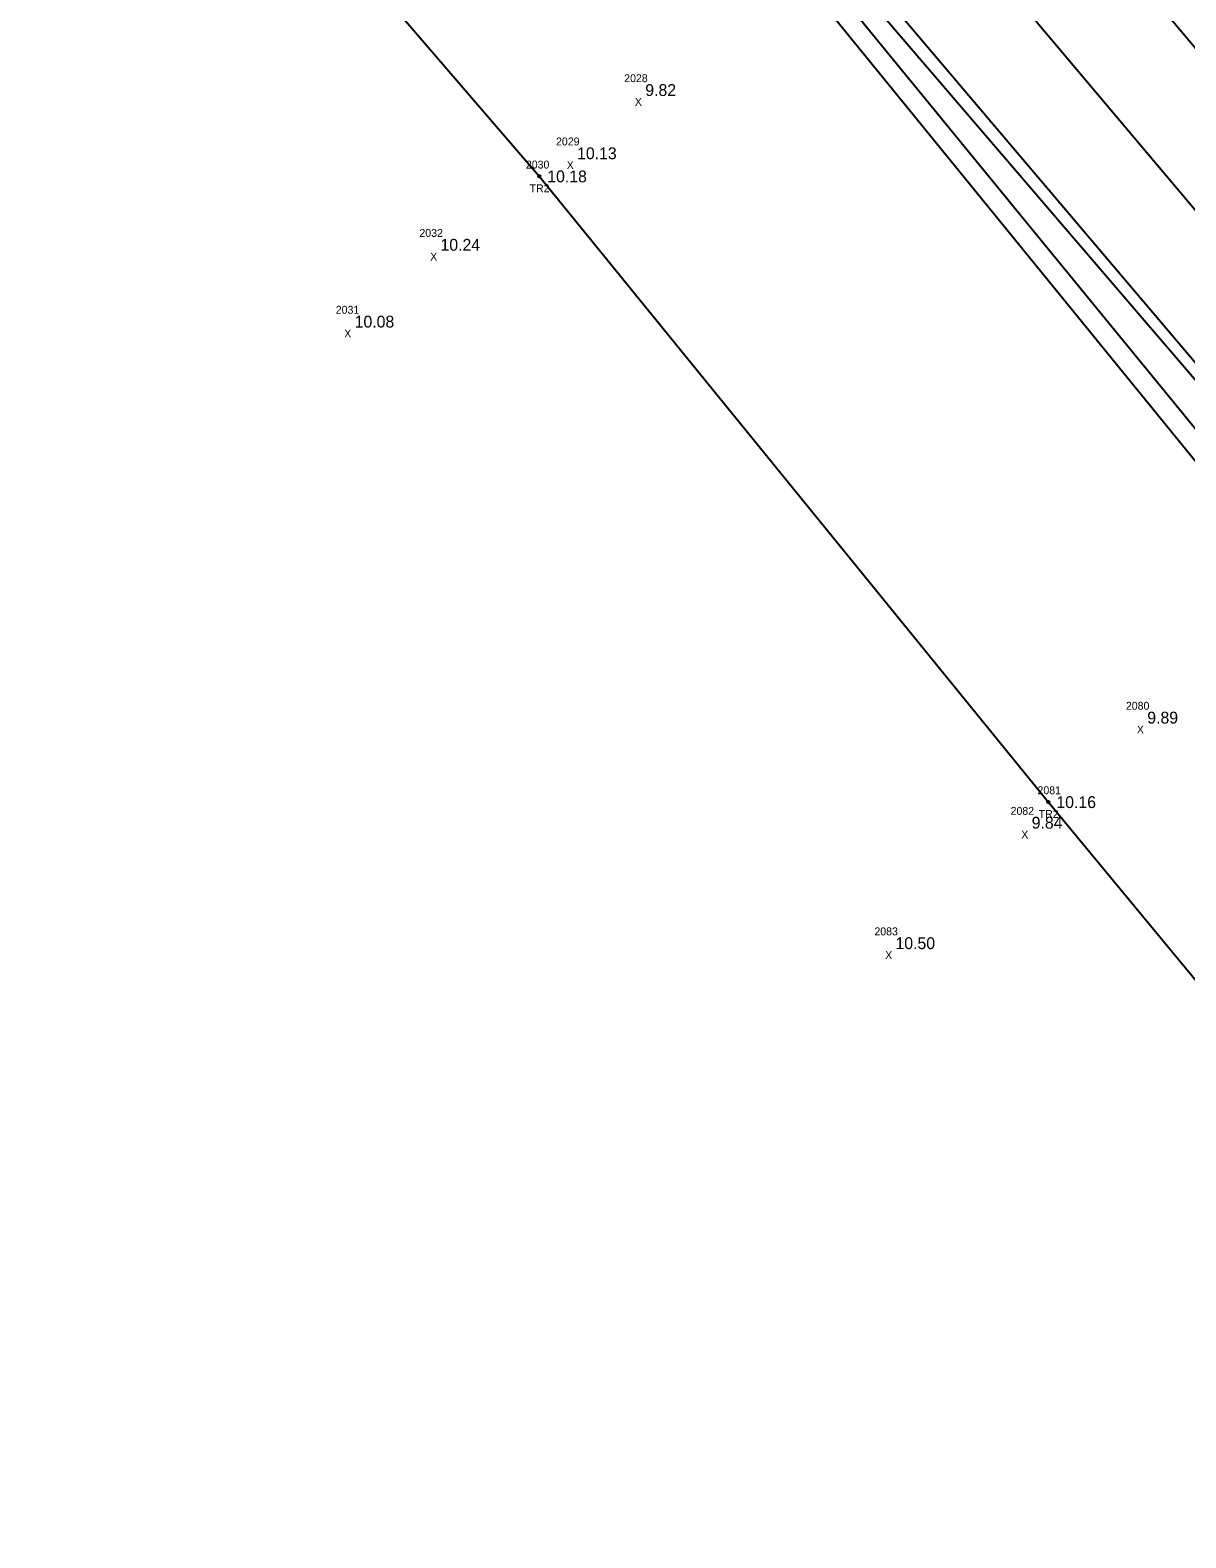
# Model space of a CAD drawing. Extents: x 2042117 to 2045853, y 303080 to 309569.
# Drawn here: x 2044074.2 to 2044220.7, y 304811.9 to 305002.9 of the extents above; entities that cross this region are included whole.
import ezdxf

# ---------------------------------------------------------------- set-up
doc = ezdxf.new("R2010")
doc.units = 0
for name, color, linetype in [('RD_EX_H2O', 7, 'Continuous'), ('RD_EX_Misc_txCode', 7, 'Continuous'), ('RD_EX_Road', 7, 'Continuous'), ('RD_EX_TX_Misc_ELEV', 7, 'Continuous'), ('RD_EX_TX_VEG_ELEV', 7, 'Continuous'), ('RD_EX_VEG', 7, 'Continuous'), ('RD_EX_VEG_txCode', 7, 'Continuous'), ('RD_HC_Cl', 7, 'Continuous'), ('RD_SMD_Locator', 7, 'Continuous')]:
    doc.layers.add(name, color=color, linetype=linetype)

msp = doc.modelspace()

# ---------------------------------------------------------------- linework, layer by layer
at = {"layer": 'RD_EX_H2O'}
for points in [[(2044112.24, 305091.58), (2044175.46, 305015.53), (2044240.61, 304938.74), (2044304.53, 304862.04), (2044368.54, 304785.1), (2044433.36, 304707.39), (2044496.86, 304631.9), (2044519.88, 304601.32), (2044518.57, 304598.19)], [(2044111.06, 305090.52), (2044173.91, 305014.56), (2044239.84, 304937.67), (2044303.17, 304860.83), (2044366.77, 304784.1), (2044432.41, 304706.69), (2044494.93, 304630.14), (2044518.25, 304599.32)], [(2044110.02, 305088.49), (2044170.14, 305011.86), (2044233.99, 304933.5), (2044300.88, 304859.21), (2044363.92, 304781.65), (2044428.82, 304703.43), (2044492.29, 304628.07), (2044516.49, 304597.96), (2044518.57, 304598.19)], [(2044110.63, 305089.46), (2044172, 305013.36), (2044236.2, 304934.93), (2044301.9, 304859.82), (2044365.31, 304782.82), (2044429.99, 304704.43), (2044493.57, 304629.27), (2044517.33, 304598.48)]]:
    msp.add_lwpolyline(points, dxfattribs=at)
at = {"layer": 'RD_EX_Road'}
msp.add_lwpolyline([(2043522.11, 305820), (2043547.67, 305789.85), (2043610.72, 305713.32), (2043674.95, 305636.32), (2043738.18, 305559.62), (2043802.42, 305482.71), (2043865.72, 305405.84), (2043929.53, 305328.85), (2043994.13, 305253.28), (2044057.4, 305176.5), (2044121.27, 305100.2), (2044185.29, 305023.54), (2044249.56, 304947.28), (2044313.31, 304870.31), (2044377.09, 304793.29), (2044442, 304716.26), (2044505.92, 304639.55), (2044570.44, 304562.35), (2044634.61, 304485.93), (2044698.46, 304409.27), (2044762.46, 304332.37)], dxfattribs=at)
at = {"layer": 'RD_EX_VEG'}
msp.add_lwpolyline([(2043442.97, 305737.07), (2043459.87, 305757.29), (2043500.33, 305735.55), (2043510.29, 305716.16), (2043558.94, 305666.15), (2043625.65, 305592.92), (2043688.91, 305518.94), (2043753.11, 305437.19), (2043818.03, 305364.7), (2043877.83, 305282.82), (2043938.63, 305211.62), (2044011.48, 305138.99), (2044075.86, 305057.44), (2044138.75, 304984.38), (2044203.27, 304905.13), (2044266.06, 304829.27), (2044328.58, 304748.23), (2044394.11, 304672.51), (2044456.79, 304595.02), (2044489.64, 304560.38)], dxfattribs=at)
at = {"layer": 'RD_HC_Cl'}
msp.add_line((2043284.3, 306123.24), (2045221.31, 303804), dxfattribs=at)
at = {"layer": 'RD_SMD_Locator'}
for centre in [(2044138.75, 304984.38), (2044203.27, 304905.13)]:
    msp.add_circle(centre, 0.15, dxfattribs=at)

# ---------------------------------------------------------------- texts
at = {"layer": 'RD_EX_Misc_txCode'}
for s, p in [('2028', (2044149.5, 304996.32)), ('X', (2044150.85, 304993.32)), ('2029', (2044140.86, 304988.31)), ('X', (2044142.22, 304985.31)), ('2032', (2044123.55, 304976.72)), ('X', (2044124.91, 304973.72)), ('2031', (2044112.95, 304966.99)), ('X', (2044114.02, 304963.99)), ('2080', (2044213.08, 304916.83)), ('X', (2044214.47, 304913.83)), ('2082', (2044198.47, 304903.52)), ('X', (2044199.82, 304900.52)), ('2083', (2044181.21, 304888.26)), ('X', (2044182.57, 304885.26))]:
    msp.add_text(s, height=1, dxfattribs=at).set_placement(p)
at = {"layer": 'RD_EX_TX_Misc_ELEV'}
for s, p in [('9.82', (2044152.17, 304994.57)), ('10.13', (2044143.53, 304986.56)), ('10.24', (2044126.22, 304974.97)), ('10.08', (2044115.34, 304965.24)), ('9.89', (2044215.79, 304915.08)), ('9.84', (2044201.14, 304901.77)), ('10.50', (2044183.88, 304886.51))]:
    msp.add_text(s, height=1.5, dxfattribs=at).set_placement(p)
at = {"layer": 'RD_EX_TX_VEG_ELEV'}
for s, p in [('10.18', (2044139.75, 304983.63)), ('10.16', (2044204.27, 304904.38))]:
    msp.add_text(s, height=1.5, dxfattribs=at).set_placement(p)
at = {"layer": 'RD_EX_VEG_txCode'}
for s, p in [('2030', (2044137.04, 304985.38)), ('TR2', (2044137.51, 304982.38)), ('2081', (2044201.88, 304906.13)), ('TR2', (2044202.03, 304903.13))]:
    msp.add_text(s, height=1, dxfattribs=at).set_placement(p)

doc.saveas('drawing.dxf')
